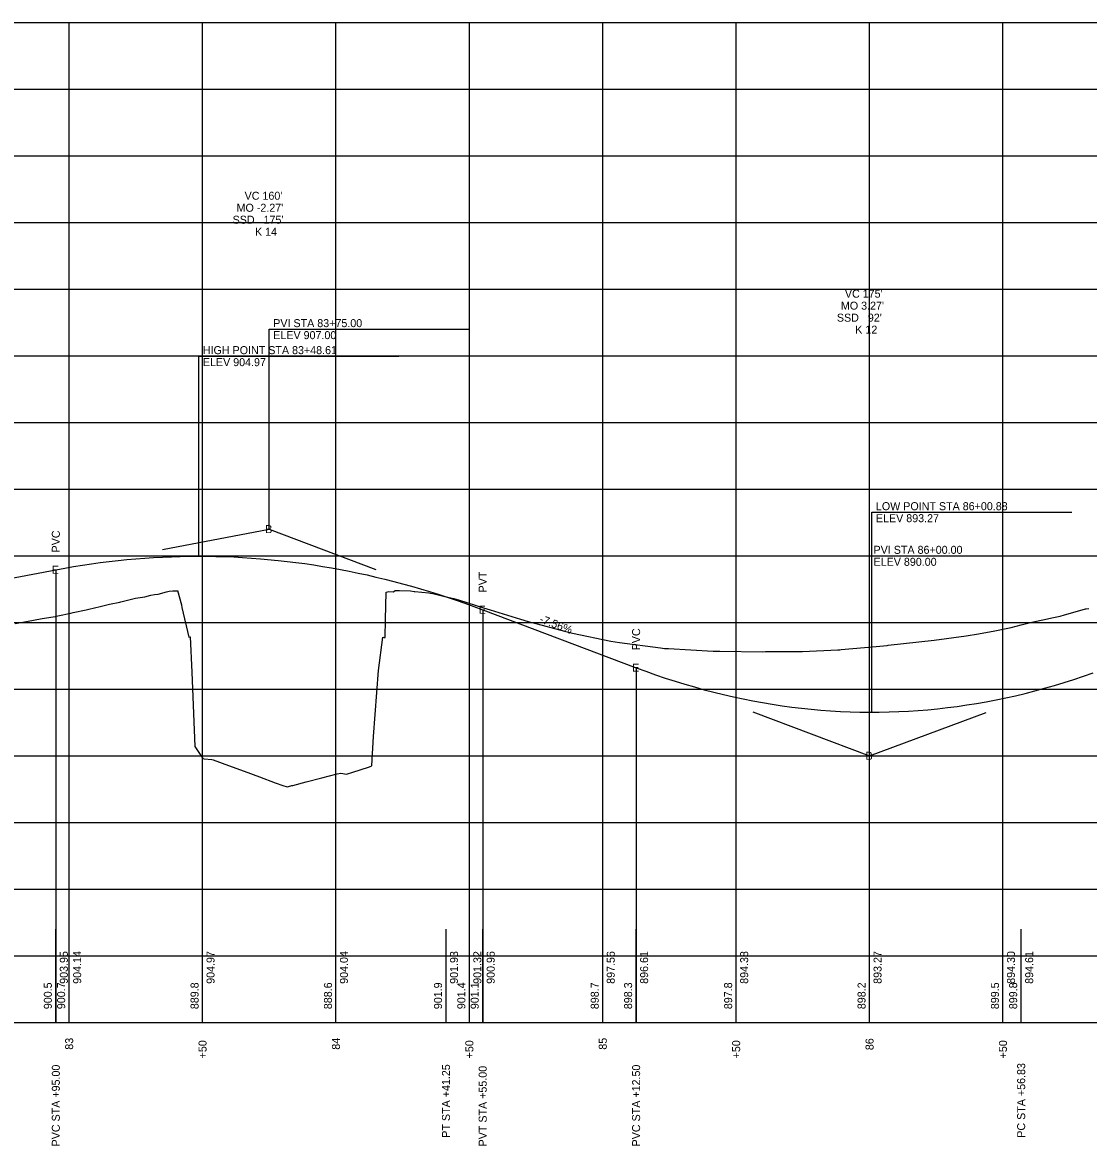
# Model space of a CAD drawing. Extents: x 76292 to 78417, y 50412 to 52585.
# Drawn here: x 76687.8 to 77087.4, y 51114.2 to 51535.3 of the extents above; entities that cross this region are included whole.
import ezdxf

# ---------------------------------------------------------------- set-up
doc = ezdxf.new("R2010")
doc.units = 0
for name, color, linetype in [('1', 7, 'Continuous'), ('2', 7, 'Continuous'), ('3', 7, 'Continuous'), ('32', 7, 'Continuous'), ('33', 7, 'Continuous'), ('63', 7, 'Continuous')]:
    doc.layers.add(name, color=color, linetype=linetype)

msp = doc.modelspace()

# ---------------------------------------------------------------- linework, layer by layer
at = {"layer": '1'}
for p, q in [((76305.34, 51160.35), (78405.34, 51160.35)), ((76705.34, 51160.35), (76705.34, 51160.35)), ((76755.34, 51160.35), (76755.34, 51160.35)), ((76805.34, 51160.35), (76805.34, 51160.35)), ((76855.34, 51160.35), (76855.34, 51160.35)), ((76905.34, 51160.35), (76905.34, 51160.35)), ((76955.34, 51160.35), (76955.34, 51160.35)), ((77005.34, 51160.35), (77005.34, 51160.35)), ((77055.34, 51160.35), (77055.34, 51160.35))]:
    msp.add_line(p, q, dxfattribs=at)
for points in [[(76780.34, 51345.35), (76780.34, 51420.35), (76855.34, 51420.35)], [(76753.95, 51335.22), (76753.95, 51410.22), (76828.95, 51410.22)], [(77006.22, 51276.71), (77006.22, 51351.71), (77081.22, 51351.71)], [(77005.34, 51260.35), (77005.34, 51335.35), (77080.34, 51335.35)], [(76700.34, 51330.12), (76700.34, 51160.35), (76700.34, 51160.35), (76700.34, 51160.35)], [(76860.34, 51315.13), (76860.34, 51160.35), (76860.34, 51160.35), (76860.34, 51160.35)], [(76917.84, 51293.4), (76917.84, 51160.35), (76917.84, 51160.35), (76917.84, 51160.35)], [(76700.34, 51160.35), (76700.34, 51195.35)], [(76700.34, 51160.35), (76700.34, 51195.35)], [(76700.34, 51160.35), (76700.34, 51195.35)], [(76700.34, 51160.35), (76700.34, 51195.35)], [(76705.34, 51160.35), (76705.34, 51195.35)], [(76705.34, 51160.35), (76705.34, 51195.35)], [(76705.34, 51160.35), (76705.34, 51195.35)], [(76705.34, 51160.35), (76705.34, 51195.35)], [(76755.34, 51160.35), (76755.34, 51195.35)], [(76755.34, 51160.35), (76755.34, 51195.35)], [(76755.34, 51160.35), (76755.34, 51195.35)], [(76755.34, 51160.35), (76755.34, 51195.35)], [(76805.34, 51160.35), (76805.34, 51195.35)], [(76805.34, 51160.35), (76805.34, 51195.35)], [(76805.34, 51160.35), (76805.34, 51195.35)], [(76805.34, 51160.35), (76805.34, 51195.35)], [(76846.59, 51160.35), (76846.59, 51195.35)], [(76846.59, 51160.35), (76846.59, 51195.35)], [(76846.59, 51160.35), (76846.59, 51195.35)], [(76846.59, 51160.35), (76846.59, 51195.35)], [(76855.34, 51160.35), (76855.34, 51195.35)], [(76855.34, 51160.35), (76855.34, 51195.35)], [(76855.34, 51160.35), (76855.34, 51195.35)], [(76855.34, 51160.35), (76855.34, 51195.35)], [(76860.34, 51160.35), (76860.34, 51195.35)], [(76860.34, 51160.35), (76860.34, 51195.35)], [(76860.34, 51160.35), (76860.34, 51195.35)], [(76860.34, 51160.35), (76860.34, 51195.35)], [(76905.34, 51160.35), (76905.34, 51195.35)], [(76905.34, 51160.35), (76905.34, 51195.35)], [(76905.34, 51160.35), (76905.34, 51195.35)], [(76905.34, 51160.35), (76905.34, 51195.35)], [(76917.84, 51160.35), (76917.84, 51195.35)], [(76917.84, 51160.35), (76917.84, 51195.35)], [(76917.84, 51160.35), (76917.84, 51195.35)], [(76917.84, 51160.35), (76917.84, 51195.35)], [(76955.34, 51160.35), (76955.34, 51195.35)], [(76955.34, 51160.35), (76955.34, 51195.35)], [(76955.34, 51160.35), (76955.34, 51195.35)], [(76955.34, 51160.35), (76955.34, 51195.35)], [(77005.34, 51160.35), (77005.34, 51195.35)], [(77005.34, 51160.35), (77005.34, 51195.35)], [(77005.34, 51160.35), (77005.34, 51195.35)], [(77005.34, 51160.35), (77005.34, 51195.35)], [(77055.34, 51160.35), (77055.34, 51195.35)], [(77055.34, 51160.35), (77055.34, 51195.35)], [(77055.34, 51160.35), (77055.34, 51195.35)], [(77055.34, 51160.35), (77055.34, 51195.35)], [(77062.17, 51160.35), (77062.17, 51195.35)], [(77062.17, 51160.35), (77062.17, 51195.35)], [(77062.17, 51160.35), (77062.17, 51195.35)], [(77062.17, 51160.35), (77062.17, 51195.35)]]:
    msp.add_lwpolyline(points, dxfattribs=at)
at = {"layer": '2'}
msp.add_lwpolyline([(76685.13, 51310), (76689.41, 51310.77), (76695.23, 51311.8), (76697.73, 51312.24), (76700.08, 51312.63), (76701.05, 51312.84), (76705.95, 51313.87), (76706.87, 51314.08), (76711.67, 51315.15), (76712.69, 51315.38), (76716.91, 51316.29), (76718.51, 51316.71), (76720.49, 51317.21), (76724.33, 51318.02), (76724.76, 51318.11), (76728.73, 51319.15), (76730.16, 51319.41), (76731.98, 51319.74), (76733.71, 51319.96), (76735.98, 51320.56), (76737.29, 51320.9), (76738.76, 51321.03), (76741.8, 51321.83), (76742.83, 51322.1), (76744.21, 51322.17), (76745.72, 51322.24), (76745.88, 51322.27), (76745.95, 51322.34), (76747.4, 51317.01), (76747.62, 51316.03), (76750.15, 51304.8), (76750.66, 51304.97), (76751.33, 51291.66), (76752.43, 51263.83), (76753.44, 51262.33), (76754.96, 51260.08), (76755.47, 51259.38), (76755.96, 51259.18), (76758.86, 51259.03), (76759.26, 51258.88), (76765.09, 51256.74), (76770.91, 51254.59), (76776.73, 51252.43), (76782.55, 51250.28), (76785.49, 51249.19), (76787.04, 51248.74), (76788.37, 51249.1), (76788.82, 51249.23), (76789.23, 51249.25), (76794.19, 51250.54), (76800.01, 51252.05), (76805.84, 51253.57), (76807.15, 51253.91), (76809.26, 51253.49), (76811.66, 51254.25), (76817.48, 51256.1), (76818.55, 51256.44), (76818.76, 51256.71), (76819.35, 51267.62), (76821.23, 51292.38), (76822.95, 51304.8), (76823.3, 51304.77), (76823.34, 51304.77), (76823.76, 51304.76), (76823.92, 51311.47), (76824.16, 51321.72), (76825.22, 51321.96), (76826.82, 51321.9), (76827.47, 51322.22), (76827.55, 51322.31), (76829.12, 51322.29), (76833.33, 51322.24), (76834.69, 51322.01), (76834.94, 51321.99), (76840.2, 51321.48), (76840.77, 51321.36), (76841.64, 51321.17), (76846.59, 51319.99), (76849.53, 51319.29), (76851.7, 51318.67), (76860.68, 51315.9), (76863.14, 51315.14), (76874.45, 51311.64), (76877.4, 51310.77), (76878.88, 51310.38), (76890.96, 51307.08), (76892.46, 51306.71), (76894.06, 51306.34), (76908.38, 51303.38), (76910.03, 51303.05), (76911.57, 51302.81), (76926.98, 51300.82), (76928.51, 51300.65), (76930.01, 51300.56), (76946.68, 51299.63), (76948, 51299.61), (76949.25, 51299.62), (76965.37, 51299.39), (76966.35, 51299.41), (76978.99, 51299.47), (76980.24, 51299.51), (76993.41, 51300.09), (76994.2, 51300.13), (76994.68, 51300.16), (77007.77, 51301.39), (77011.88, 51301.73), (77012.32, 51301.8), (77029.54, 51303.77), (77041.52, 51305.38), (77046.22, 51306.1), (77052.31, 51307.16), (77058.4, 51308.45), (77062.17, 51309.41), (77066.22, 51310.44), (77067.32, 51310.72), (77070.27, 51311.35), (77074.32, 51312.22), (77076.77, 51312.75), (77078.37, 51313.2), (77082.42, 51314.35), (77086.23, 51315.43), (77086.47, 51315.46), (77087.51, 51315.59)], dxfattribs=at)
at = {"layer": '32'}
for p, q in [((76630.34, 51316.79), (76700.34, 51330.12)), ((76860.34, 51315.13), (76917.84, 51293.4))]:
    msp.add_line(p, q, dxfattribs=at)
for points in [[(76740.34, 51337.73), (76780.34, 51345.35), (76820.34, 51330.24)], [(76700.34, 51330.12), (76703.67, 51330.73), (76707.01, 51331.31), (76710.34, 51331.84), (76713.67, 51332.34), (76717.01, 51332.8), (76720.34, 51333.21), (76723.67, 51333.59), (76727.01, 51333.93), (76730.34, 51334.23), (76733.67, 51334.49), (76737.01, 51334.71), (76740.34, 51334.89), (76743.67, 51335.03), (76747.01, 51335.14), (76750.34, 51335.2), (76753.67, 51335.22), (76757.01, 51335.2), (76760.34, 51335.15), (76763.67, 51335.05), (76767.01, 51334.92), (76770.34, 51334.74), (76773.67, 51334.53), (76777.01, 51334.28), (76783.67, 51333.65), (76787.01, 51333.28), (76790.34, 51332.87), (76793.67, 51332.42), (76797.01, 51331.93), (76800.34, 51331.4), (76803.67, 51330.83), (76807.01, 51330.22), (76810.34, 51329.58), (76813.67, 51328.89), (76817.01, 51328.16), (76820.34, 51327.4), (76823.67, 51326.59), (76827.01, 51325.75), (76830.34, 51324.86), (76833.67, 51323.94), (76837.01, 51322.97), (76840.34, 51321.97), (76843.67, 51320.93), (76847.01, 51319.85), (76850.34, 51318.73), (76853.67, 51317.57), (76857.01, 51316.36), (76860.34, 51315.13)], [(76917.84, 51293.4), (76921.49, 51292.05), (76925.13, 51290.76), (76928.78, 51289.53), (76932.42, 51288.35), (76936.07, 51287.23), (76939.71, 51286.16), (76943.36, 51285.15), (76947.01, 51284.2), (76950.65, 51283.31), (76954.3, 51282.47), (76957.94, 51281.69), (76961.59, 51280.97), (76965.24, 51280.3), (76968.88, 51279.69), (76972.53, 51279.14), (76976.17, 51278.64), (76979.82, 51278.2), (76983.46, 51277.82), (76987.11, 51277.49), (76990.76, 51277.22), (76994.4, 51277.01), (76998.05, 51276.85), (77001.69, 51276.75), (77008.99, 51276.72), (77012.63, 51276.8), (77016.28, 51276.92), (77019.92, 51277.11), (77023.57, 51277.35), (77027.21, 51277.65), (77030.86, 51278.01), (77034.51, 51278.42), (77038.15, 51278.89), (77041.8, 51279.41), (77045.44, 51280), (77049.09, 51280.64), (77052.74, 51281.33), (77056.38, 51282.09), (77060.03, 51282.9), (77063.67, 51283.76), (77067.32, 51284.69), (77070.96, 51285.67), (77074.61, 51286.7), (77078.26, 51287.8), (77081.9, 51288.95), (77085.55, 51290.16), (77089.19, 51291.42)], [(76961.59, 51276.88), (77005.34, 51260.35), (77049.09, 51276.55)]]:
    msp.add_lwpolyline(points, dxfattribs=at)
at = {"layer": '63'}
for p, q in [((76305.34, 51535.35), (78405.34, 51535.35)), ((76305.34, 51535.35), (78405.34, 51535.35)), ((76705.34, 51160.35), (76705.34, 51535.35)), ((76755.34, 51160.35), (76755.34, 51535.35)), ((76805.34, 51160.35), (76805.34, 51535.35)), ((76855.34, 51160.35), (76855.34, 51535.35)), ((76905.34, 51160.35), (76905.34, 51535.35)), ((76955.34, 51160.35), (76955.34, 51535.35)), ((77005.34, 51160.35), (77005.34, 51535.35)), ((77055.34, 51160.35), (77055.34, 51535.35)), ((76305.34, 51510.35), (78405.34, 51510.35)), ((76305.34, 51485.35), (78405.34, 51485.35)), ((76305.34, 51460.35), (78405.34, 51460.35)), ((76305.34, 51435.35), (78405.34, 51435.35)), ((76305.34, 51410.35), (78405.34, 51410.35)), ((76305.34, 51385.35), (78405.34, 51385.35)), ((76305.34, 51360.35), (78405.34, 51360.35)), ((76305.34, 51335.35), (78405.34, 51335.35)), ((76305.34, 51310.35), (78405.34, 51310.35)), ((76305.34, 51285.35), (78405.34, 51285.35)), ((76305.34, 51260.35), (78405.34, 51260.35)), ((76305.34, 51235.35), (78405.34, 51235.35)), ((76305.34, 51210.35), (78405.34, 51210.35)), ((76305.34, 51185.35), (78405.34, 51185.35))]:
    msp.add_line(p, q, dxfattribs=at)

# ---------------------------------------------------------------- texts
at = {"layer": '1'}
for s, p in [('83', (76706.84, 51150.15)), ('+50', (76756.84, 51146.89)), ('84', (76806.84, 51150.15)), ('+50', (76856.84, 51146.89)), ('85', (76906.84, 51150.15)), ('+50', (76956.84, 51146.89)), ('86', (77006.84, 51149.98)), ('+50', (77056.84, 51146.89))]:
    msp.add_text(s, height=3, rotation=90, dxfattribs=at).set_placement(p)
at = {"layer": '3'}
for s, p in [('900.5', (76698.84, 51165.35)), ('900.7', (76703.84, 51165.35)), ('889.8', (76753.84, 51165.35)), ('888.6', (76803.84, 51165.35)), ('901.9', (76845.09, 51165.35)), ('901.4', (76853.84, 51165.35)), ('901.1', (76858.84, 51165.35)), ('898.7', (76903.84, 51165.35)), ('898.3', (76916.34, 51165.35)), ('897.8', (76953.84, 51165.35)), ('898.2', (77003.84, 51165.35)), ('899.5', (77053.84, 51165.35)), ('899.8', (77060.67, 51165.35))]:
    msp.add_text(s, height=3, rotation=90, dxfattribs=at).set_placement(p)
at = {"layer": '33'}
for s, p in [("VC 160'", (76771.1, 51468.87)), ("MO -2.27'", (76768.1, 51464.37)), ("SSD   175'", (76766.6, 51459.87)), ('K 14', (76774.99, 51455.37)), ("VC 175'", (76996.1, 51432.15)), ("MO 3.27'", (76994.6, 51427.65)), ("SSD   92'", (76993.1, 51423.15)), ('K 12', (76999.99, 51418.65)), ('B', (76778.84, 51343.85)), ('B', (77003.84, 51258.85))]:
    msp.add_text(s, height=3, dxfattribs=at).set_placement(p)
for s, rotation, p in [('PVI STA 83+75.00', 360, (76781.84, 51421.1)), ('ELEV 907.00', 360, (76781.84, 51416.6)), ('HIGH POINT STA 83+48.61', 360, (76755.45, 51410.97)), ('ELEV 904.97', 360, (76755.45, 51406.47)), ('LOW POINT STA 86+00.88', 360, (77007.72, 51352.46)), ('ELEV 893.27', 360, (77007.72, 51347.96)), ('PVC', 90, (76701.84, 51336.62)), ('PVI STA 86+00.00', 360, (77006.84, 51336.1)), ('ELEV 890.00', 360, (77006.84, 51331.6)), ('E', 360, (76698.84, 51328.62)), ('PVT', 90, (76861.84, 51321.63)), ('E', 360, (76858.84, 51313.63)), ('-7.56%', 339.3045, (76881.4, 51310.47)), ('PVC', 90, (76919.34, 51299.9)), ('E', 360, (76916.34, 51291.9)), ('903.95', 90, (76704.84, 51174.85)), ('904.14', 90, (76709.84, 51174.85)), ('904.97', 90, (76759.84, 51174.85)), ('904.04', 90, (76809.84, 51174.85)), ('901.93', 90, (76851.09, 51174.85)), ('901.32', 90, (76859.84, 51174.85)), ('900.96', 90, (76864.84, 51174.85)), ('897.56', 90, (76909.84, 51174.85)), ('896.61', 90, (76922.34, 51174.85)), ('894.38', 90, (76959.84, 51174.85)), ('893.27', 90, (77009.84, 51174.85)), ('894.30', 90, (77059.84, 51174.85)), ('894.61', 90, (77066.67, 51174.85)), ('PVC STA +95.00', 90, (76701.84, 51113.89)), ('PT STA +41.25', 90, (76848.09, 51117.15)), ('PVT STA +55.00', 90, (76861.84, 51113.89)), ('PVC STA +12.50', 90, (76919.34, 51113.89)), ('PC STA +56.83', 90, (77063.67, 51117.15))]:
    msp.add_text(s, height=3, rotation=rotation, dxfattribs=at).set_placement(p)

doc.saveas('drawing.dxf')
